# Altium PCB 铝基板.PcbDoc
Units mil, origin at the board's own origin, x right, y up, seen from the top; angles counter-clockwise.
Board outline 354.33 x 771.65 mil, 2 copper layers (Top Layer, Bottom Layer); 4 components, 2 nets, 12 pads, 0 vias.
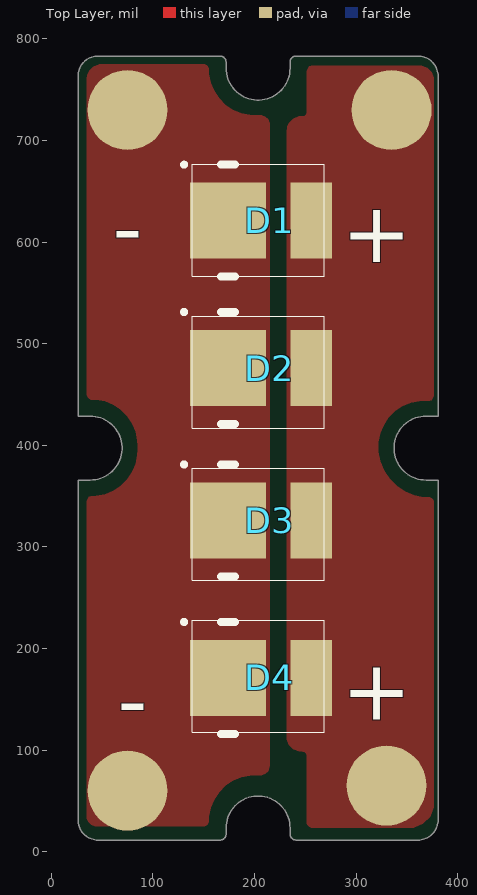
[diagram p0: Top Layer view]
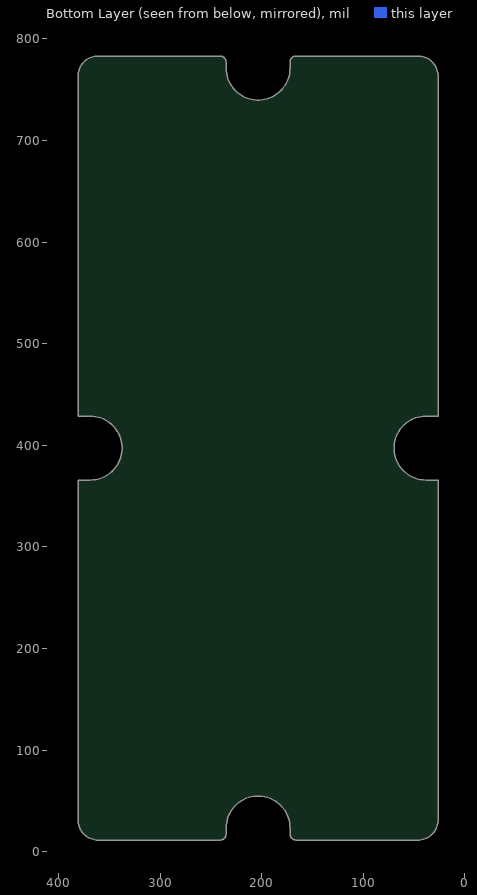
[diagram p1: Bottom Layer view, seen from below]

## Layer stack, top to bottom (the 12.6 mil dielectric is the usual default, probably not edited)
Top Solder: solder mask 0.4, Solder Resist, Dk 3.5
Top Layer: signal copper 1.4
Dielectric 1: dielectric 12.6, FR-4, Dk 4.8
Bottom Layer: signal copper 1.4
Bottom Solder: solder mask 0.4, Solder Resist, Dk 3.5

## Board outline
26.42,31.07 ccw(c46.1,31.07) 46.1,11.39 166.18,11.39 ccw(c166.18,17.29) 172.08,17.29 172.08,23.2 cw(c203.58,23.2) 235.08,23.2 235.08,17.29 ccw(c240.98,17.29) 240.98,11.39 361.06,11.39 ccw(c361.06,31.07) 380.75,31.07 380.75,365.72 368.94,365.72 cw(c368.94,397.22) 368.94,428.71 380.75,428.71 380.75,763.36 ccw(c361.06,763.36) 361.06,783.04 240.98,783.04 ccw(c240.98,777.14) 235.08,777.14 235.08,771.23 cw(c203.58,771.23) 172.08,771.23 172.08,777.14 ccw(c166.18,777.14) 166.18,783.04 46.1,783.04 ccw(c46.1,763.36) 26.42,763.36 26.42,428.71 38.23,428.71 cw(c38.23,397.22) 38.23,365.72 26.42,365.72

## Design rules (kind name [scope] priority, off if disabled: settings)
Clearance [All] p1: gap=10 ignorepadtopadclearanceinfootprint=FALSE except(0: Arc-Hole Track-Hole SMDPad-Hole THPad-Hole Via-Hole Fill-Hole Poly-Hole Region-Hole Text-Hole)
PlaneConnect [All] p1: planeconnectstyle=Direct reliefexpansion=20 reliefentries=4 reliefconductorwidth=10 reliefairgap=10
PolygonConnect [All] p1: connectstyle=Direct reliefconductorwidth=10 reliefentries=4 polygonreliefangle="90 Angle" airgapwidth=10
RoutingVias [All] p1: holewidth=28 width=50 viastyle="Through Hole" minholewidth=28 minwidth=50 maxholewidth=28 maxwidth=50
SolderMaskExpansion [All] p1: expansion=4
Width [All] p1: maxlimit=10 minlimit=10 preferedwidth=10
29 further rules are at their usual default settings.

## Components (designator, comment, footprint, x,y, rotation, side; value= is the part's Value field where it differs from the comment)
D1 "LED3" 3528-L 174.11,621 r0 top
D2 "LED3" 3528-L 174.11,476 r0 top
D3 "LED3" 3528-L 174.11,326 r0 top
D4 "LED3" 3528-L 174.11,171 r0 top

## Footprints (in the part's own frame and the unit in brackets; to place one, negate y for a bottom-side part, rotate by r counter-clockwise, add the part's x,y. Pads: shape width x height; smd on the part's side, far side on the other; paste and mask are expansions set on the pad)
3528-L [mm]
  rect 1.03x1.9 smd: 1(2.08,0)
  rect 1.9x1.9 smd: 2(0,0)
  silkscreen extent -1.15,-1.4 0.17,1.45, body extent -0.8,-1.4 2.4,1.4, height 1.8

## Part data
D1 D2 D3 D4: "Typical BLUE SiC LED"

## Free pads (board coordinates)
  round 78.74 smd: 1(75,60) 1(75,730) 1(330,65) 1(335,730)

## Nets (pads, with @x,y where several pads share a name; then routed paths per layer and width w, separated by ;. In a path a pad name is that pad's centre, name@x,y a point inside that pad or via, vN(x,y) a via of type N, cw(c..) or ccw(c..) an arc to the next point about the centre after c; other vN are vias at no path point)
GND: D1.2 D2.2 D3.2 D4.2 pad.1@75,60 pad.1@75,730
VCC: D1.1 D2.1 D3.1 D4.1 pad.1@330,65 pad.1@335,730

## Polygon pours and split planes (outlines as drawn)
VCC on Top Layer "Mechanical 1-No Net" (solid, remove dead copper, pour order 0): 351.72,23.65 ccw(c351.72,48.65) 376.72,48.65 376.72,343.65 ccw(c371.72,343.65) 371.72,348.65 cw(c371.72,398.65) 321.72,398.65 cw(c366.72,398.65) 366.72,443.65 371.72,443.65 ccw(c371.72,448.65) 376.72,448.65 376.72,758.65 ccw(c361.72,758.65) 361.72,773.65 256.72,773.65 ccw(c256.72,768.65) 251.72,768.65 251.72,728.65 cw(c246.72,728.65) 246.72,723.65 ccw(c246.72,708.65) 231.72,708.65 231.72,113.65 ccw(c246.72,113.65) 246.72,98.65 cw(c246.72,93.65) 251.72,93.65 251.72,28.65 ccw(c256.72,28.65) 256.72,23.65
GND on Top Layer "Mechanical 1-No Net" (solid, remove dead copper, pour order 2): 45,25 150,25 ccw(c150,30) 155,30 cw(c200,30) 200,75 205,75 ccw(c205,85) 215,85 215,715 ccw(c205,715) 205,725 200,725 cw(c200,770) 155,770 ccw(c150,770) 150,775 50,775 ccw(c50,760) 35,760 35,450 ccw(c40,450) 40,445 cw(c40,400) 85,400 85,395 cw(c40,395) 40,350 ccw(c40,345) 35,345 35,35 ccw(c45,35)

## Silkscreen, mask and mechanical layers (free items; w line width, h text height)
Top Overlay:
  lines w0.5: 138.62,117.69 268.54,117.69 268.54,227.92 138.62,227.92 138.62,117.69 ; 138.62,267.29 268.54,267.29 268.54,377.53 138.62,377.53 138.62,267.29 ; 138.62,416.9 268.54,416.9 268.54,527.14 138.62,527.14 138.62,416.9 ; 138.62,566.51 268.54,566.51 268.54,676.74 138.62,676.74 138.62,566.51
  text "-" at 90,585 h60
  text "+" at 355,580 h60
  text "+" at 355,130 h60
  text "-" at 95,120 h60
Top Solder:
  text "RM" at 360,480 h39.37 r90
  text "RM" at 50,310 h39.37 r270
Mechanical 1:
  the board outline again, w0.5
Mechanical 15:
  lines w0.5: 26.42,339.35 ccw(c38.23,397.22) 26.42,455.08 ; 145.72,11.39 cw(c203.58,23.2) 261.44,11.39 ; 145.72,783.04 ccw(c203.58,771.23) 261.44,783.04 ; 380.75,339.35 cw(c368.94,397.22) 380.75,455.08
